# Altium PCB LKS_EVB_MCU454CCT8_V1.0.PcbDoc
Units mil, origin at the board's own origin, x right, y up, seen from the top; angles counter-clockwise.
Board outline 2625 x 1560 mil, 2 copper layers (Top Layer, Bottom Layer); 47 components, 59 nets, 200 pads, 105 vias.
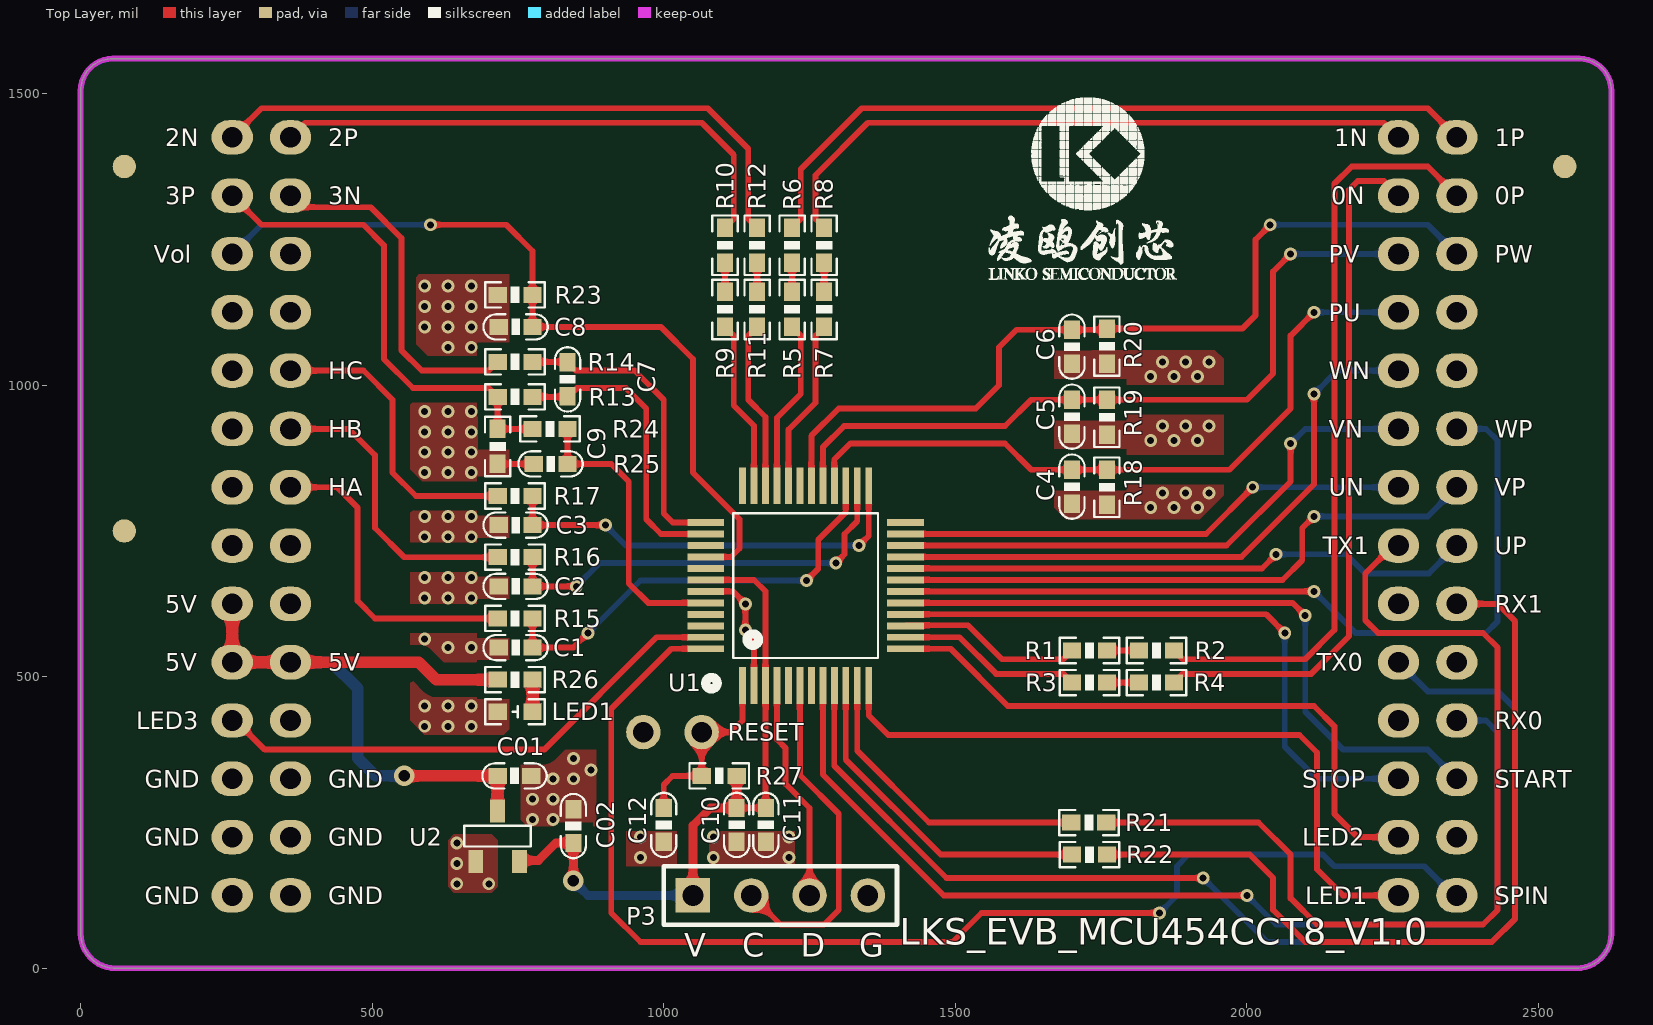
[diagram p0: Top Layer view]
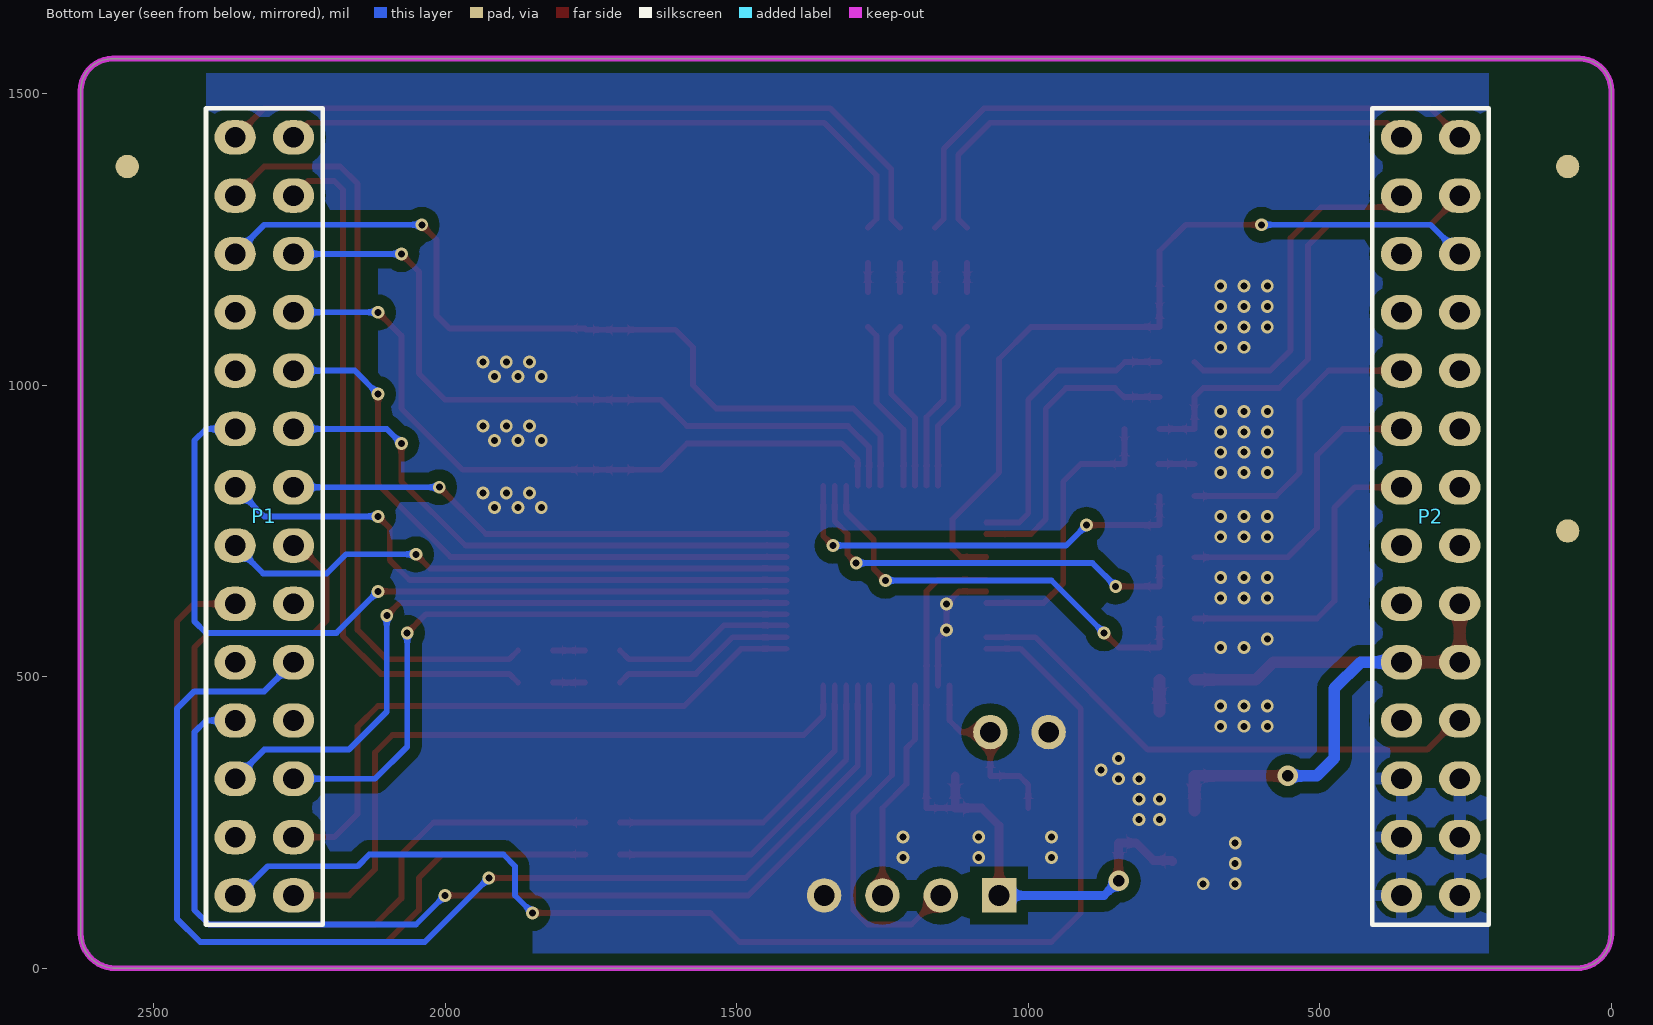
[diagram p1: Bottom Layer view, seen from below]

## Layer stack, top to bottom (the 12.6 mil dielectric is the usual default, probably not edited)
Top Solder: solder mask 0.4, Solder Resist, Dk 3.5
Top Layer: signal copper 1.4
Dielectric1: dielectric 12.6, FR-4, Dk 4.8
Bottom Layer: signal copper 1.4
Bottom Solder: solder mask 0.4, Solder Resist, Dk 3.5

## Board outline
0,60 0,1505 cw(c55,1505) 55,1560 2570,1560 cw(c2570,1505) 2625,1505 2625,60 cw(c2565,60) 2565,0 60,0 cw(c60,60)

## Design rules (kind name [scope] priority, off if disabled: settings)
Clearance Clearance_2 [InPolygon] p1: gap=20 ignorepadtopadclearanceinfootprint=FALSE except(0: Arc-Hole Track-Hole SMDPad-Hole THPad-Hole Via-Hole Fill-Hole Poly-Hole Region-Hole Text-Hole)
Clearance Clearance_1 [All] p2: gap=7.87 ignorepadtopadclearanceinfootprint=FALSE except(0: Arc-Hole Track-Hole SMDPad-Hole THPad-Hole Via-Hole Fill-Hole Poly-Hole Region-Hole Text-Hole)
ComponentClearance [All] p1: gap=0 collisioncheckmode=3 verticalgap=0 showdistances=FALSE
DiffPairsRouting [All] p1: maxlimit=10 minlimit=10 mostfreqgap=10 toplayer_minwidth=8 toplayer_maxwidth=15 toplayer_prefwidth=10 bottomlayer_minwidth=8 bottomlayer_maxwidth=15 bottomlayer_prefwidth=10 maxuncoupledlength=500
FabricationTestpoint [(IsPad And (OnTopLayer Or OnBottomLayer))] p1: side=3 testpointundercomponent=TRUE minsize=40 maxsize=100 preferedsize=60 minholesize=0 maxholesize=40 preferedholesize=32 testpointgrid=1 allowsidetop=TRUE allowsidebottom=TRUE usegrid=TRUE gridtolerance=0.01
HoleSize [All] p1: absolutevalues=TRUE maxlimit=100 minlimit=0 maxpercent=80.000 minpercent=20.000
PolygonConnect PolygonConnect_1 [HasFootprint('HDR 2X14 顶层') vs InNet('GND')] p1: connectstyle=Relief reliefconductorwidth=20 reliefentries=4 polygonreliefangle="90 Angle" airgapwidth=10
PolygonConnect [All] p2: connectstyle=Direct reliefconductorwidth=10 reliefentries=4 polygonreliefangle="90 Angle" airgapwidth=10
RoutingVias [All] p1: holewidth=28 width=50 viastyle="Through Hole" minholewidth=0 minwidth=10 maxholewidth=28 maxwidth=50
SilkToSolderMaskClearance SilkscreenOverComponentPads [IsPad] p1: minsilkscreentomaskgap=10 clearancetoexposedcopper=TRUE
SolderMaskExpansion [All] p1: expansion=4 istentingtop=FALSE
Width [All] p1: maxlimit=100 minlimit=1 preferedwidth=10
25 further rules are at their usual default settings.

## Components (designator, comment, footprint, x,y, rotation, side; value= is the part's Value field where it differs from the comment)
C1 "10nF/16V" 0603C 746,550 r180 top
C01 "10uF/16V" 0603C 744.05,330 r180 top
C2 "10nF/16V" 0603C 746,655 r180 top
C02 "10uF/10V" 0603C 845,244.06 r270 top
C3 "10nF/16V" 0603C 746,760 r180 top
C4 "1nF/16V" 0603C 1700,826 r270 top
C5 "1nF/16V" 0603C 1700,946 r270 top
C6 "1nF/16V" 0603C 1700,1066 r270 top
C7 "1nF/10V" 0603C 835,1010 r90 top
C8 "100nF/50V" 0603C 745.94,1100 r0 top
C9 "1nF/50V" 0603C 805.94,865 r0 top
C10 "10uF/10V" 0603C 1125,245.95 r90 top
C11 "100nF/50V" 0603C 1175,245.95 r90 top
C12 "100nF/50V" 0603C 1000,246 r270 top
LED1 "LED" "LED 0603R" 745,440 r180 top
P1 "Header 14X2A" "HDR 2X14 顶层" 2310,775 r180 bottom locked
P2 "Header 14X2A" "HDR 2X14 顶层" 310,775 r180 bottom locked
P3 "Header 4" "HDR 1X4" 1050,125 r0 top
R1 "20K1%" 0603R 1730,545 r180 top value=K
R2 "20K1%" 0603R 1845,545 r180 top value=K
R3 "20K1%" 0603R 1730,490 r180 top value=K
R4 "20K1%" 0603R 1845,490 r180 top value=K
R5 "20K1%" 0603R 1220,1130 r270 top value=K
R6 "20K1%" 0603R 1220,1240 r270 top value=K
R7 "20K1%" 0603R 1275,1130 r270 top value=K
R8 "20K1%" 0603R 1275,1240 r270 top value=K
R9 "20K1%" 0603R 1105,1130 r270 top value=K
R10 "20K1%" 0603R 1105,1240 r270 top value=K
R11 "20K1%" 0603R 1160,1130 r270 top value=K
R12 "20K1%" 0603R 1160,1240 r270 top value=K
R13 "1K1%" 0603R 745,980 r0 top value=K
R14 "1K1%" 0603R 745,1040 r0 top value=K
R15 "2K" 0603R 745,600 r0 top value=K
R16 "2K" 0603R 745,705 r0 top value=K
R17 "2K" 0603R 745,810 r0 top value=K
R18 "1K" 0603R 1760,825 r270 top value=K
R19 "1K" 0603R 1760,945 r270 top value=K
R20 "1K" 0603R 1760,1066.95 r270 top value=K
R21 "10R" 0603R 1729.06,250 r180 top value=K
R22 "10R" 0603R 1730,195 r0 top value=K
R23 "1K1%" 0603R 745,1155 r0 top value=K
R24 "1K1%" 0603R 805,925 r180 top value=K
R25 "10R" 0603R 715,895 r270 top value=K
R26 "330R" 0603R 745,495 r0 top value=330
R27 "20K" 0603R 1095,330 r0 top value=K
U1 "LKS32MC454CCT8" TQFP48 1243.27,656.26 r0 top locked
U2 "XC6206P332MR" SOT-23 715,226.69 r0 top

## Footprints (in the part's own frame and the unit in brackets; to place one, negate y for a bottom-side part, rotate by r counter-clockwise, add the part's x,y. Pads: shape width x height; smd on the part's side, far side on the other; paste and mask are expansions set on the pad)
0603C [mm] "电容"
  rect 0.8x0.7 smd: 1(-0.737,0) 2(0.738,0)
  silkscreen extent -1.4,-0.55 1.4,0.55, body extent -0.8,-0.41 0.8,0.41, height 0.81
0603R [mm] "电阻"
  rect 0.8x0.7 smd: 1(-0.762,0) 2(0.762,0)
  silkscreen extent -1.3,-0.55 1.3,0.55, body extent -0.8,-0.4 0.8,0.4, height 0.45
"HDR 1X4" [mm] "单排针 2.54mm"
  rect 1.5x1.5 hole 0.9: 1(0,0)
  round 1.5 hole 0.9: 2(2.54,0) 3(5.08,0) 4(7.62,0)
  silkscreen extent -1.27,-1.27 8.89,1.27, body extent -1.27,-1.27 8.89,1.27, height 8.5
"HDR 2X14 顶层" [mm] "双排针 2.54mm 顶层"
  oval 1.8x1.5 hole 0.9: 1(1.27,16.51) 2(1.27,13.97) 3(1.27,11.43) 4(1.27,8.89) 5(1.27,6.35) 6(1.27,3.81) 7(1.27,1.27) 8(1.27,-1.27) 9(1.27,-3.81) 10(1.27,-6.35) 11(1.27,-8.89) 12(1.27,-11.43) 13(1.27,-13.97) 14(1.27,-16.51) 15(-1.27,16.51) 16(-1.27,13.97) 17(-1.27,11.43) 18(-1.27,8.89) 19(-1.27,6.35) 20(-1.27,3.81) 21(-1.27,1.27) 22(-1.27,-1.27) 23(-1.27,-3.81) 24(-1.27,-6.35) 25(-1.27,-8.89) 26(-1.27,-11.43) 27(-1.27,-13.97) 28(-1.27,-16.51)
  silkscreen extent -2.54,-17.78 2.54,17.78, body extent -2.54,-17.78 2.54,17.78, height 8.5
"LED 0603R" [mm] "LED"
  rect 0.8x0.7 smd: 1(-0.762,0) 2(0.762,0)
  silkscreen extent -1.3,-0.55 1.3,0.55, body extent -0.8,-0.4 0.8,0.4, height 0.47
SOT-23 [mm]
  rect 0.65x1 smd: 1(-0.95,-1.1) 2(0.95,-1.1) 3(0,1.1)
  silkscreen extent -1.45,-0.45 1.45,0.45, body extent -1.5,-1.2 1.5,1.2, height 1.05
TQFP48 [mm] "MCU"
  rect 0.3x1.6 smd: 1(-2.75,-4.35) 2(-2.25,-4.35) 3(-1.75,-4.35) 4(-1.25,-4.35) 5(-0.75,-4.35) 6(-0.25,-4.35) 7(0.25,-4.35) 8(0.75,-4.35) 9(1.25,-4.35) 10(1.75,-4.35) 11(2.25,-4.35) 12(2.75,-4.35) 25(2.75,4.35) 26(2.25,4.35) 27(1.75,4.35) 28(1.25,4.35) 29(0.75,4.35) 30(0.25,4.35) 31(-0.25,4.35) 32(-0.75,4.35) 33(-1.25,4.35) 34(-1.75,4.35) 35(-2.25,4.35) 36(-2.75,4.35)
  rect 1.6x0.3 smd: 13(4.35,-2.75) 14(4.35,-2.25) 15(4.35,-1.75) 16(4.35,-1.25) 17(4.35,-0.75) 18(4.35,-0.25) 19(4.35,0.25) 20(4.35,0.75) 21(4.35,1.25) 22(4.35,1.75) 23(4.35,2.25) 24(4.35,2.75) 37(-4.35,2.75) 38(-4.35,2.25) 39(-4.35,1.75) 40(-4.35,1.25) 41(-4.35,0.75) 42(-4.35,0.25) 43(-4.35,-0.25) 44(-4.35,-0.75) 45(-4.35,-1.25) 46(-4.35,-1.75) 47(-4.35,-2.25) 48(-4.35,-2.75)
  silkscreen extent -4.35,-4.5 3.15,3.15, body extent -4.5,-4.5 4.5,4.5, height 1.05

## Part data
C1 C2 C3 C4 C5 C6: library part CAP, "Capacitor"
C01 C02 C7 C8 C9 C10 C11 C12: library part C, "Capacitor"
LED1: "LED_Light"
P1 P2: "Header, 14-Pin, Dual row"
P3: "Header, 4-Pin"
R1 R2 R3 R4 R5 R6 R7 R8 R9 R10 R11 R12 R13 R14 R15 R16 R17 R18 R19 R20 R21 R22 R23 R24 R25 R26 R27: library part Res, "Resistor"
U1: "芯片"
U2: library part 7805

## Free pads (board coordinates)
  round 59.06 hole 35.43: 0(1065,405) 1(965,405)
  round 40 all layers, no hole: 1(75,1375) 2(2545,1375) 3(75,750)

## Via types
v1: diameter 22, hole 12, Top Layer to Bottom Layer, 103 vias
v2: diameter 35, hole 20, Top Layer to Bottom Layer, 2 vias

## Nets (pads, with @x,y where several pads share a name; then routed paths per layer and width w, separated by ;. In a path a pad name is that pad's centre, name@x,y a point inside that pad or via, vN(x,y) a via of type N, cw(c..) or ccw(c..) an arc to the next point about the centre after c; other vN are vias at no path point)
+3.3V: C02.2 C10.2 C11.2 P3.1 R27.2 U1.3 U1.42 U2.2 | length 1180.8
  Top Layer w10: U1.42 1154.9,666.1 1174.37,646.63 U1.3 1174.68,484.69 1174.68,275.32 C11.2 C10.2
  Top Layer w15: U2.2 754.01,185 785,185 815,215 C02.2 v2(845,150) ; P3.1 1050,245 1080,275 C10.2 R27.2
  Bottom Layer w15: v2(845,150) 870,125 P3.1
+5V: C01.2 P2.9 P2.10 P2.24 R26.1 U2.3 | length 1133.5
  Top Layer w20: P2.9 P2.10 P2.24 580,525 610,495 R26.1 ; v2(555,330) C01.2 U2.3
  Bottom Layer w20: P2.24 430,525 475,480 475,360 505,330 v2(555,330)
GND: C01.1 C1.2 C02.1 C2.2 C3.2 C4.2 C5.2 C6.2 C8.1 C9.1 C10.1 C11.1 C12.2 LED1.2 P2.12 P2.13 P2.14 P2.26 P2.27 P2.28 P3.4 pad.1@965,405 R18.2 R19.2 R20.2 R23.1 R25.2 U1.2 U1.43 U2.1 | length 284.9
  Top Layer w10: R25.2 C9.1 ; U1.43 1118.58,646.42 v1(1140,625) v1(1140,580) 1154.69,565.31 U1.2
  other v1: 645,145 700,145 645,180 960,190 1085,190 1215,190 645,215 960,225 1085,225 1215,225 775,255 810,255 775,290 810,290 810,325 845,325 875,340 845,360 590,415 630,415 670,415 590,450 630,450 670,450 630,550 670,550 590,565 590,635 630,635 670,635 590,670 630,670 670,670 590,740 630,740 670,740 590,775 630,775 670,775 1835,790 1875,790 1915,790 1855,815 1895,815 1935,815 590,850 630,850 670,850 590,885 630,885 670,885 1835,905 1875,905 1915,905 590,920 630,920 670,920 1855,930 1895,930 1935,930 590,955 630,955 670,955 1835,1015 1875,1015 1915,1015 1855,1040 1895,1040 1935,1040 630,1065 670,1065 590,1100 630,1100 670,1100 590,1135 630,1135 670,1135 590,1170 630,1170 670,1170
GND0: P2.16 R14.1 | length 598.2
  Top Layer w10: P2.16 379.99,1305 497.43,1305 550,1252.43 550,1060 585,1025 700,1025 R14.1
HALL_U: C1.1 R15.2 U1.27 | length 758
  Top Layer w10: R15.2 C1.1 845,550 v1(870,575) ; v1(1245,665) 1265,685 1265,735 1312.17,782.17 U1.27
  Bottom Layer w10: v1(870,575) 960,665 v1(1245,665)
HALL_V: C2.1 R16.2 U1.26 | length 734.4
  Top Layer w10: R16.2 C2.1 v1(850,655) ; v1(1295,695) 1310,710 1310,745 1331.85,766.85 U1.26
  Bottom Layer w10: v1(850,655) 890,695 v1(1295,695)
HALL_W: C3.1 R17.2 U1.25 | length 733.9
  Top Layer w10: R17.2 C3.1 v1(900,760) ; v1(1335,725) 1351.54,741.54 U1.25
  Bottom Layer w10: v1(900,760) 935,725 v1(1335,725)
HU: P2.21 R15.1 | length 541.9
  Top Layer w10: P2.21 440,825 475,790 475,630 505,600 R15.1
HV: P2.20 R16.1 | length 519.4
  Top Layer w10: P2.20 460,925 505,880 505,755 555,705 R16.1
HW: P2.19 R17.1 | length 517.3
  Top Layer w10: P2.19 485,1025 535,975 535,850 575,810 R17.1
LED1: P1.14 U1.12 | length 1204.9
  Top Layer w10: U1.12 1351.54,433.46 1385,400 2090,400 2120,370 2120,170 2165,125 P1.14
LED2: P1.13 U1.13 | length 1067.1
  Top Layer w10: U1.13 1492.01,547.99 1590,450 2115,450 2150,415 2150,265 2190,225 P1.13
LED3: P2.11 U1.47 | length 912.5
  Top Layer w10: P2.11 265.91,425 315.91,375 795,375 987.68,567.68 U1.47
NetLED1_1: LED1.1 R26.2 | length 55
  Top Layer w20: LED1.1 R26.2
NetR1_1: R1.1 R2.2 | length 55
  Top Layer w10: R1.1 R2.2
NetR3_1: R3.1 R4.2 | length 55
  Top Layer w10: R3.1 R4.2
NetR5_1: R5.1 R6.2 | length 50
  Top Layer w10: R5.1 R6.2
NetR7_1: R7.1 R8.2 | length 50
  Top Layer w10: R7.1 R8.2
NetR9_1: R9.1 R10.2 | length 50
  Top Layer w10: R9.1 R10.2
NetR11_1: R11.1 R12.2 | length 50
  Top Layer w10: R11.1 R12.2
NetR21_2: R21.2 U1.11 | length 531
  Top Layer w10: U1.11 1331.85,373.15 1455,250 R21.2@1700,250
NetR22_1: R22.1 U1.10 | length 582.4
  Top Layer w10: U1.10 1312.17,357.83 1475,195 R22.1
NRST: C12.1 pad.0 R27.1 U1.1 | length 324.5
  Top Layer w10: C12.1 1000,315 1015,330 R27.1 pad.0 1115,405 1135,425 U1.1
OC: C9.2 R24.1 U1.44 | length 498.2
  Top Layer w10: R24.1 C9.2 910,865 940,835 940,660 973.27,626.73 U1.44
OPA1_IN: C7.2 R14.2 U1.37 | length 525.3
  Top Layer w10: R14.2 834.05,1040 C7.2 849.05,1025 950,1025 1000,975 1000,780 1015.47,764.53 U1.37
OPA1_IP: C7.1 R13.2 U1.38 | length 519.2
  Top Layer w10: R13.2 834,980 C7.1 ; C7.1@835,978.51 851.49,995 935,995 970,960 970,770 995.16,744.84 U1.38
OPA2_IN: R11.2 U1.34 | length 290.9
  Top Layer w10: R11.2 1145,1085 1145,975 1174.37,945.63 U1.34
OPA2_IP: R9.2 U1.35 | length 293.1
  Top Layer w10: R9.2 1120,1085 1120,965 1154.68,930.32 U1.35
OPA3_IN: R7.2 U1.32 | length 297.9
  Top Layer w10: U1.32 1213.74,923.74 1260,970 1260,1085 R7.2
OPA3_IP: R5.2 U1.33 | length 295.7
  Top Layer w10: U1.33 1194.06,944.06 1235,985 1235,1085 R5.2
OPA5_IN: R3.2 U1.14 | length 317.6
  Top Layer w10: U1.14 1507.32,567.68 1570,505 1685,505 R3.2
OPA5_IP: R1.2 U1.15 | length 316.2
  Top Layer w10: U1.15 1415.43,588.27 1521.73,588.27 1580,530 1685,530 R1.2
P0.0: P2.22
PGND0: P1.2 R4.1 | length 1199.9
  Top Layer w10: R4.1 1890,505 2110.36,505 2175,569.64 2175,1335 2190,1350 2235,1350 P1.2
PGND1: P1.1 R8.1 | length 1143.8
  Top Layer w10: R8.1 1260,1285 1260,1360 1350,1450 2235,1450 P1.1
PGND2: P2.1 R12.1 | length 1076.1
  Top Layer w10: P2.1 310,1475 1075.36,1475 1145,1405.36 1145,1285 R12.1
PGND3: P2.2 R13.1 R24.2 R25.1 | length 827.1
  Top Layer w10: P2.2 310,1275 485,1275 520,1240 520,1045 570,995 700,995 R13.1 R25.1 R24.2
PU: C4.1 P1.4 R18.1 U1.28 | length 1227.6
  Top Layer w10: U1.28 1292.48,872.48 1320,900 1585,900 1630,855 C4.1 R18.1 1970,855 2075,960 2075,1085 v1(2115,1125)
  Bottom Layer w10: v1(2115,1125) P1.4
PV: C5.1 P1.3 R19.1 U1.29 | length 1293
  Top Layer w10: U1.29 1272.8,893.52 1309.28,930 1585,930 1630,975 C5.1 R19.1 2000,975 2045,1020 2045,1195 v1(2075,1225)
  Bottom Layer w10: v1(2075,1225) P1.3
PW: C6.1 P1.17 R20.1 U1.30 | length 1477.3
  Top Layer w10: U1.30 1253.11,913.11 1300,960 1535,960 1575,1000 1575,1065 1605,1095 C6.1 1758.05,1095 R20.1 1991.94,1096.95 2015,1120 2015,1250 v1(2040,1275)
  Bottom Layer w10: v1(2040,1275) 2310,1275 P1.17
RXD0: P1.25 U1.8 | length 1810.2
  Top Layer w10: U1.8 1272.8,332.2 1480,125 v1(2000,125)
  Bottom Layer w10: v1(2000,125) 2050,75 2405,75 2430,100 2430,404.99 2409.99,425 P1.25
RXD1: P1.23 R22.2 | length 1434.3
  Top Layer w10: R22.2@1759.06,195 2005,195 2045,155 2045,100 2100,45 2420,45 2460,85 2460,595 2430,625 P1.23
SPIN: P1.28 U1.48 | length 2145.8
  Top Layer w10: U1.48 1012.99,547.99 910,445 910,95 960,45 1495,45 1545,95 v1(1850,95)
  Bottom Layer w10: v1(1850,95) 1880,125 1880,175 1900,195 2130,195 2150,175 2304.09,175 2354.09,125 P1.28
START1: P1.26 U1.17 | length 1167.1
  Top Layer w10: U1.17 2078.27,626.73 v1(2100,605)
  Bottom Layer w10: v1(2100,605) 2100,440 2165,375 2310,375 P1.26
STOP1: P1.12 U1.16 | length 1079.4
  Top Layer w10: U1.16 2032.95,607.05 v1(2065,575) ; P1.12@2258,323 P1.12
  Bottom Layer w10: v1(2065,575) 2065,380 2120,325 P1.12
SWCLK: P3.2 U1.6 | length 593.6
  Top Layer w10: P3.2 1200,75 1275,75 1300,100 1300,265 1233.43,331.57 U1.6
SWDIO: P3.3 U1.4 | length 383.2
  Top Layer w10: U1.4 1194.06,392.22 1209,377.28 1209,316 1250,275 P3.3
TXD0: P1.10 U1.9 | length 2040
  Top Layer w10: U1.9 1292.48,347.52 1485,155 v1(1925,155)
  Bottom Layer w10: v1(1925,155) 2035,45 2420,45 2460,85 2460,445 2430,475 2310,475 P1.10
TXD1: P1.8 R21.1 | length 1651.1
  Top Layer w10: R21.1 2020,250 2075,195 2075,120 2120,75 2405,75 2430,100 2430,550 2405,575 2225,575 2203,597 2203,677 2251,725 P1.8
UN: P1.7 U1.23 | length 878.7
  Top Layer w10: U1.23 1929.84,744.84 v1(2010,825)
  Bottom Layer w10: v1(2010,825) P1.7
UP: P1.22 U1.20 | length 989.1
  Top Layer w10: U1.20 2025.79,685.79 v1(2050,710)
  Bottom Layer w10: v1(2050,710) 2170,710 2203,677 2312,677 P1.22
UP-: P2.15 R10.1 | length 924.4
  Top Layer w10: P2.15 385,1450 1065,1450 1120,1395 1120,1285 R10.1
VN: P1.6 U1.22 | length 966.3
  Top Layer w10: U1.22 1965.16,725.16 2075,835 v1(2075,900)
  Bottom Layer w10: v1(2075,900) 2100,925 P1.6
VOL_ADC: C8.2 P2.3 R23.2 U1.40 | length 1404.3
  Top Layer w10: v1(600,1275) 730,1275 775,1230 R23.2 C8.2 995,1100 1050,1045 1050,850 1130,770 1130,720 1115.47,705.47 U1.40
  Bottom Layer w10: P2.3 310,1275 v1(600,1275)
VP: P1.21 U1.19 | length 1043.5
  Top Layer w10: U1.19 2061.1,666.1 2095,700 2095,755 v1(2115,775)
  Bottom Layer w10: v1(2115,775) 2310,775 P1.21
VP-: P1.15 R6.1 | length 1295.6
  Top Layer w10: R6.1 1235,1285 1235,1370.36 1339.64,1475 2309.99,1475 P1.15
WN: P1.5 U1.21 | length 1068.6
  Top Layer w10: U1.21 1990.47,705.47 2115,830 v1(2115,985)
  Bottom Layer w10: v1(2115,985) 2155,1025 P1.5
WP: P1.20 U1.18 | length 1441.6
  Top Layer w10: U1.18 v1(2115,646.42)
  Bottom Layer w10: v1(2115,646.42) 2186.42,575 2410,575 2430,595 2430,904.99 2409.99,925 P1.20
WP-: P1.16 R2.1 | length 1310.3
  Top Layer w10: R2.1 1890,530 2100,530 2150,580 2150,1345.36 2179.64,1375 2309.99,1375 P1.16
pads on no net: P1.9 P1.11 P1.18 P1.19 P1.24 P1.27 P2.4 P2.5 P2.6 P2.7 P2.8 P2.17 P2.18 P2.23 P2.25 U1.5 U1.7 U1.24 U1.31 U1.36 U1.39 U1.41 U1.45 U1.46

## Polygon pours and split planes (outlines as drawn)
GND on Top Layer "10" (solid, remove dead copper, pour order 11): 735,1190 735,410 725,400 590,400 565,425 565,1175 580,1190
GND on Top Layer "10" (solid, remove dead copper, pour order 7): 1670,1060 1945,1060 1960,1045 1960,810 1915,765 1695,765 1670,790
GND on Top Layer "10" (solid, remove dead copper, pour order 12): 630,220 640,230 705,230 715,220 715,140 705,130 640,130 630,140
GND on Top Layer "10" (solid, remove dead copper, pour order 10): 755,375 755,255 765.95,244.05 904.05,244.05 910,250 910,355 890,375
GND on Top Layer "10" (solid, remove dead copper, pour order 9): 910,235 1025,235 1025,175 910,175
GND on Top Layer "10" (solid, remove dead copper, pour order 8): 1050,235 1250,235 1250,175 1050,175
GND on Bottom Layer "Top Layer-No Net 1" (solid, remove dead copper, pour order 6): 210,1560 210,0 2410,0 2410,1560

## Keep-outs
Keep-Out Layer:
  the board outline again, w10

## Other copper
Bottom Layer:
  pour cut-out: 2115,1125 2115,1225 2150,1225 2150,1125
  pour cut-out: 2115,985 2115,1125 2150,1125 2150,1020
  pour cut-out: 2075,825 2075,900 2100,900 2100,825
  pour cut-out: 1850,95 1850,0 1875,0 1875,95

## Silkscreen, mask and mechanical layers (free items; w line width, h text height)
Top Overlay:
  drawing of 144 lines, arcs and shapes, not listed
  text "2N" at 145,1410 h30
  text "2P" at 425,1410 h30
  text "1N" at 2150,1410 h30
  text "1P" at 2425,1410 h30
  text "3P" at 145,1310 h30
  text "3N" at 425,1310 h30
  text "0N" at 2145,1310 h30
  text "0P" at 2425,1310 h30
  text "Vol" at 125,1210 h30
  text "PV" at 2140,1210 h30
  text "PW" at 2425,1210 h30
  text "PU" at 2140,1110 h30
  text "HC" at 425,1010 h30
  text "WN" at 2140,1010 h30
  text "HB" at 425,910 h30
  text "VN" at 2140,910 h30
  text "WP" at 2425,910 h30
  text "HA" at 425,810 h30
  text "UN" at 2140,810 h30
  text "VP" at 2425,810 h30
  text "TX1" at 2130,710 h30
  text "UP" at 2425,710 h30
  text "5V" at 145,610 h30
  text "RX1" at 2425,610 h30
  text "5V" at 145,510 h30
  text "5V" at 425,510 h30
  text "TX0" at 2120,510 h30
  text "LED3" at 95,410 h30
  text "RX0" at 2425,410 h30
  text "RESET" at 1110,390 h30
  text "GND" at 110,310 h30
  text "GND" at 425,310 h30
  text "STOP" at 2095,310 h30
  text "START" at 2425,310 h30
  text "GND" at 110,210 h30
  text "GND" at 425,210 h30
  text "LED2" at 2095,210 h30
  text "GND" at 110,110 h30
  text "GND" at 425,110 h30
  text "LED1" at 2100,110 h30
  text "SPIN" at 2425,110 h30
  text "LKS_EVB_MCU454CCT8_V1.0" at 1405,25 h78.74
  text "V" at 1035,20 h40
  text "C" at 1135,20 h40
  text "D" at 1235,20 h40
  text "G" at 1335,20 h40
Top Solder:
  circle w78: c75,750 r17
  circle w78: c2545,1375 r17
  circle w78: c75,1375 r17
Mechanical 1:
  the board outline again, w10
